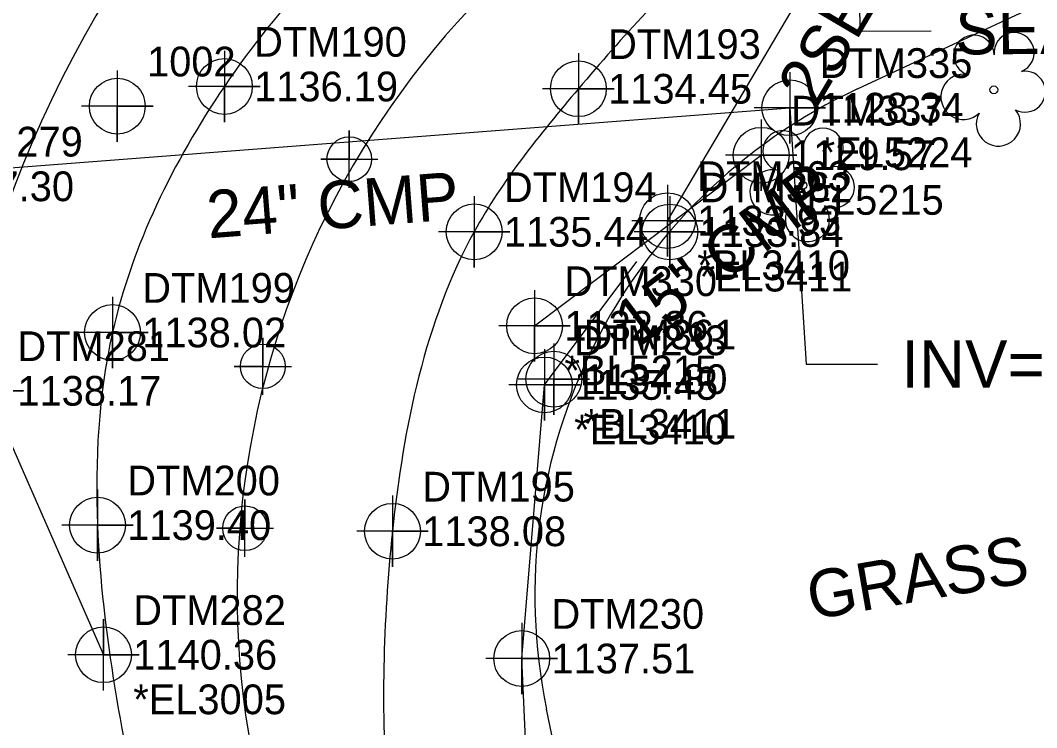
# Model space of a CAD drawing. Extents: x 1286007 to 1287145, y 857718 to 858514.
# Drawn here: x 1286494.9 to 1286580.3, y 858055.9 to 858115.3 of the extents above; entities that cross this region are included whole.
import ezdxf

# ---------------------------------------------------------------- set-up
doc = ezdxf.new("R2010")
doc.units = 0
for name, color, linetype in [('Default Symbol CELL', 7, 'Continuous'), ('Default Symbol Cogo Number', 7, 'Continuous'), ('Exist Horizontal Alignment', 7, 'Continuous'), ('Exist Other Culture Fence Line', 7, 'Continuous'), ('Exist Other Culture Fence Line Cogo Comment', 7, 'Continuous'), ('Exist Other Culture Fence Line Cogo Elevation', 7, 'Continuous'), ('Exist Other Culture Fence Line Cogo Number', 7, 'Continuous'), ('Exist Other Culture Fence Line Cogo Point CELL', 7, 'Continuous'), ('Exist Other Culture Fence Line Text', 7, 'Continuous'), ('Exist Other Culture Gate Cogo Comment', 7, 'Continuous'), ('Exist Other Culture Gate Cogo Elevation', 7, 'Continuous'), ('Exist Other Culture Gate Cogo Number', 7, 'Continuous'), ('Exist Other Culture Gate Cogo Point CELL', 7, 'Continuous'), ('Exist Right of Way Line', 7, 'Continuous'), ('Exist Roads EOP', 7, 'Continuous'), ('Exist Roads EOP Cogo Elevation', 7, 'Continuous'), ('Exist Roads EOP Cogo Number', 7, 'Continuous'), ('Exist Roads EOP Cogo Point CELL', 7, 'Continuous'), ('Exist Roads Soil', 7, 'Continuous'), ('Exist Roads Soil Cogo Comment', 7, 'Continuous'), ('Exist Roads Soil Cogo Elevation', 7, 'Continuous'), ('Exist Roads Soil Cogo Number', 7, 'Continuous'), ('Exist Roads Soil Cogo Point CELL', 7, 'Continuous'), ('Exist Structure Major Bridge Seat Top Elevation', 7, 'Continuous'), ('Exist Structure Minor Pipes CMP 15 Inch', 7, 'Continuous'), ('Exist Structure Minor Pipes CMP 15 Inch Cogo Comment', 7, 'Continuous'), ('Exist Structure Minor Pipes CMP 15 Inch Cogo Elevation', 7, 'Continuous'), ('Exist Structure Minor Pipes CMP 15 Inch Cogo Number', 7, 'Continuous'), ('Exist Structure Minor Pipes CMP 15 Inch Cogo Point CELL', 7, 'Continuous'), ('Exist Structure Minor Pipes CMP 15 Inch Text', 7, 'Continuous'), ('Exist Structure Minor Pipes CMP 24 Inch', 7, 'Continuous'), ('Exist Structure Minor Pipes CMP 24 Inch Cogo Comment', 7, 'Continuous'), ('Exist Structure Minor Pipes CMP 24 Inch Cogo Elevation', 7, 'Continuous'), ('Exist Structure Minor Pipes CMP 24 Inch Cogo Number', 7, 'Continuous'), ('Exist Structure Minor Pipes CMP 24 Inch Cogo Point CELL', 7, 'Continuous'), ('Exist Structure Minor Pipes CMP 24 Inch Invert', 7, 'Continuous'), ('Exist Structure Minor Pipes CMP 24 Inch Text', 7, 'Continuous'), ('Exist Vegetation Tree CELL', 7, 'Continuous'), ('Exist Vegetation Tree Text', 7, 'Continuous'), ('Old_Level_20', 7, 'Continuous')]:
    doc.layers.add(name, color=color, linetype=linetype)

msp = doc.modelspace()

# ---------------------------------------------------------------- linework, layer by layer
at = {"layer": 'Default Symbol CELL'}
for points in [[(1286503.055, 858111.112), (1286503.055, 858105.112), (1286503.055, 858108.112), (1286506.055, 858108.112), (1286500.055, 858108.112)], [(1286503.055, 858111.112), (1286503.055, 858105.112), (1286503.055, 858108.112), (1286506.055, 858108.112), (1286500.055, 858108.112)], [(1286522.535, 858101.26), (1286522.535, 858106.06), (1286522.535, 858103.66), (1286520.135, 858103.66), (1286524.935, 858103.66)], [(1286515.277, 858083.844), (1286515.277, 858088.644), (1286515.277, 858086.244), (1286512.877, 858086.244), (1286517.677, 858086.244)], [(1286513.778, 858070.239), (1286513.778, 858075.039), (1286513.778, 858072.639), (1286511.378, 858072.639), (1286516.178, 858072.639)]]:
    msp.add_lwpolyline(points, dxfattribs=at)
for centre, radius in [((1286503.055, 858108.112), 2.344), ((1286503.055, 858108.112), 2.344), ((1286522.535, 858103.66), 1.875), ((1286515.277, 858086.244), 1.875), ((1286513.778, 858072.639), 1.875)]:
    msp.add_circle(centre, radius, dxfattribs=at)
at = {"layer": 'Exist Horizontal Alignment'}
msp.add_arc((1286585.125, 858066.987), 72, 115.04397, 191.72533, dxfattribs=at)
at = {"layer": 'Exist Other Culture Fence Line'}
msp.add_line((1286549.257, 858098.489), (1286564.961, 858125.103), dxfattribs=at)
for points in [[(1286538.924, 858084.683), (1286546.692, 858095.062)], [(1286547.407, 857964.989), (1286539.472, 858022.106), (1286538.051, 858038.903), (1286537.017, 858061.685), (1286538.924, 858084.683)]]:
    msp.add_lwpolyline(points, dxfattribs=at)
at = {"layer": 'Exist Other Culture Fence Line Cogo Point CELL'}
for points in [[(1286549.257, 858101.489), (1286549.257, 858095.489), (1286549.257, 858098.489), (1286552.257, 858098.489), (1286546.257, 858098.489)], [(1286538.924, 858087.683), (1286538.924, 858081.683), (1286538.924, 858084.683), (1286541.924, 858084.683), (1286535.924, 858084.683)], [(1286537.017, 858064.685), (1286537.017, 858058.685), (1286537.017, 858061.685), (1286540.017, 858061.685), (1286534.017, 858061.685)]]:
    msp.add_lwpolyline(points, dxfattribs=at)
for centre in [(1286549.257, 858098.489), (1286538.924, 858084.683), (1286537.017, 858061.685)]:
    msp.add_circle(centre, 2.344, dxfattribs=at)
at = {"layer": 'Exist Other Culture Gate Cogo Point CELL'}
for points in [[(1286549.458, 858100.537), (1286549.458, 858094.537), (1286549.458, 858097.537), (1286552.458, 858097.537), (1286546.458, 858097.537)], [(1286539.713, 858088.163), (1286539.713, 858082.163), (1286539.713, 858085.163), (1286542.713, 858085.163), (1286536.713, 858085.163)]]:
    msp.add_lwpolyline(points, dxfattribs=at)
for centre in [(1286549.458, 858097.537), (1286539.713, 858085.163)]:
    msp.add_circle(centre, 2.344, dxfattribs=at)
at = {"layer": 'Exist Right of Way Line'}
for p, q in [((1286565.23, 858109.569), (1286654.285, 858151.179)), ((1286558.704, 857963.01), (1286539.106, 858057.436))]:
    msp.add_line(p, q, dxfattribs=at)
for radius in [97, 47]:
    msp.add_arc((1286585.125, 858066.987), radius, 115.04397, 191.72533, dxfattribs=at)
at = {"layer": 'Exist Roads EOP'}
for points in [[(1286554.506, 858138.221), (1286544.419, 858134.401), (1286528.832, 858126.933), (1286512.047, 858109.768), (1286502.652, 858089.088), (1286501.393, 858072.897), (1286505.471, 858045.649), (1286512.056, 858016.522), (1286519.805, 857984.681), (1286525.58, 857958.7)], [(1286561.061, 858127.479), (1286553.633, 858121.854), (1286541.776, 858109.576), (1286533.023, 858097.553), (1286526.163, 858072.381), (1286525.732, 858049.679), (1286530.491, 858019.74), (1286536.523, 857989.722), (1286542.222, 857961.323)]]:
    msp.add_spline(points, degree=3, dxfattribs=at)
at = {"layer": 'Exist Roads EOP Cogo Point CELL'}
for points in [[(1286512.047, 858112.768), (1286512.047, 858106.768), (1286512.047, 858109.768), (1286515.047, 858109.768), (1286509.047, 858109.768)], [(1286541.776, 858112.576), (1286541.776, 858106.576), (1286541.776, 858109.576), (1286544.776, 858109.576), (1286538.776, 858109.576)], [(1286533.023, 858100.553), (1286533.023, 858094.553), (1286533.023, 858097.553), (1286536.023, 858097.553), (1286530.023, 858097.553)], [(1286502.652, 858092.088), (1286502.652, 858086.088), (1286502.652, 858089.088), (1286505.652, 858089.088), (1286499.652, 858089.088)], [(1286501.393, 858075.897), (1286501.393, 858069.897), (1286501.393, 858072.897), (1286504.393, 858072.897), (1286498.393, 858072.897)], [(1286526.163, 858075.381), (1286526.163, 858069.381), (1286526.163, 858072.381), (1286529.163, 858072.381), (1286523.163, 858072.381)]]:
    msp.add_lwpolyline(points, dxfattribs=at)
for centre in [(1286512.047, 858109.768), (1286541.776, 858109.576), (1286533.023, 858097.553), (1286502.652, 858089.088), (1286501.393, 858072.897), (1286526.163, 858072.381)]:
    msp.add_circle(centre, 2.344, dxfattribs=at)
at = {"layer": 'Exist Roads Soil'}
msp.add_lwpolyline([(1286451.264, 858136.048), (1286463.084, 858125.359), (1286484.836, 858101.378), (1286492.165, 858084.188), (1286501.894, 858062.005)], dxfattribs=at)
at = {"layer": 'Exist Roads Soil Cogo Point CELL'}
for points in [[(1286492.165, 858081.188), (1286492.165, 858087.188), (1286492.165, 858084.188), (1286495.165, 858084.188), (1286489.165, 858084.188)], [(1286501.894, 858059.005), (1286501.894, 858065.005), (1286501.894, 858062.005), (1286504.894, 858062.005), (1286498.894, 858062.005)]]:
    msp.add_lwpolyline(points, dxfattribs=at)
msp.add_circle((1286501.894, 858062.005), 2.344, dxfattribs=at)
at = {"layer": 'Exist Structure Major Bridge Seat Top Elevation'}
msp.add_lwpolyline([(1286565.278, 858126.616), (1286565.417, 858114.423), (1286571.417, 858114.452)], dxfattribs=at)
at = {"layer": 'Exist Structure Minor Pipes CMP 15 Inch'}
msp.add_line((1286538.1, 858089.65), (1286557.128, 858103.986), dxfattribs=at)
at = {"layer": 'Exist Structure Minor Pipes CMP 15 Inch Cogo Point CELL'}
for points in [[(1286557.128, 858106.986), (1286557.128, 858100.986), (1286557.128, 858103.986), (1286560.128, 858103.986), (1286554.128, 858103.986)], [(1286538.1, 858092.65), (1286538.1, 858086.65), (1286538.1, 858089.65), (1286541.1, 858089.65), (1286535.1, 858089.65)]]:
    msp.add_lwpolyline(points, dxfattribs=at)
for centre in [(1286557.128, 858103.986), (1286538.1, 858089.65)]:
    msp.add_circle(centre, 2.344, dxfattribs=at)
at = {"layer": 'Exist Structure Minor Pipes CMP 24 Inch'}
msp.add_line((1286469.96, 858101.075), (1286559.538, 858107.984), dxfattribs=at)
at = {"layer": 'Exist Structure Minor Pipes CMP 24 Inch Cogo Point CELL'}
msp.add_lwpolyline([(1286559.538, 858110.984), (1286559.538, 858104.984), (1286559.538, 858107.984), (1286562.538, 858107.984), (1286556.538, 858107.984)], dxfattribs=at)
msp.add_circle((1286559.538, 858107.984), 2.344, dxfattribs=at)
at = {"layer": 'Exist Structure Minor Pipes CMP 24 Inch Invert'}
msp.add_lwpolyline([(1286559.538, 858107.984), (1286560.897, 858086.441), (1286566.897, 858086.441)], dxfattribs=at)
at = {"layer": 'Exist Vegetation Tree CELL'}
for p, q in [((1286576.666, 858109.487), (1286576.666, 858109.487)), ((1286560.627, 858101.459), (1286560.627, 858101.459))]:
    msp.add_line(p, q, dxfattribs=at)
for centre in [(1286576.666, 858109.487), (1286560.627, 858101.459)]:
    msp.add_circle(centre, 0.326, dxfattribs=at)
for centre, radius, start, end in [((1286574.993, 858112.386), 1.698, 1.28216, 254.55999), ((1286578.37, 858112.608), 1.689, 291.56708, 186.23104), ((1286574.117, 858108.898), 1.899, 77.1011, 314.19993), ((1286579.271, 858109.333), 1.727, 242.66361, 99.3457), ((1286577.05, 858106.613), 1.856, 150.16508, 39.71335), ((1286558.954, 858104.358), 1.698, 1.28216, 254.55999), ((1286562.331, 858104.579), 1.689, 291.56708, 186.23104), ((1286563.232, 858101.305), 1.727, 242.66361, 99.3457), ((1286558.078, 858100.87), 1.899, 77.1011, 314.19993), ((1286561.012, 858098.585), 1.856, 150.16508, 39.71335)]:
    msp.add_arc(centre, radius, start, end, dxfattribs=at)
at = {"layer": 'Old_Level_20'}
msp.add_arc((1286585.125, 858066.987), 72, 115.04397, 191.72533, dxfattribs=at)

# ---------------------------------------------------------------- texts
at = {"layer": 'Default Symbol Cogo Number'}
msp.add_text('1002', height=2.5, dxfattribs=at).set_placement((1286505.555, 858110.612))
at = {"layer": 'Exist Other Culture Fence Line Cogo Comment'}
for s, p in [('*BL3410', (1286551.757, 858093.489)), ('*EL3410', (1286541.424, 858079.683))]:
    msp.add_text(s, height=2.5, dxfattribs=at).set_placement(p)
at = {"layer": 'Exist Other Culture Fence Line Cogo Elevation'}
for s, p in [('1133.93', (1286551.757, 858097.239)), ('1135.45', (1286541.424, 858083.433)), ('1137.51', (1286539.517, 858060.435))]:
    msp.add_text(s, height=2.5, dxfattribs=at).set_placement(p)
at = {"layer": 'Exist Other Culture Fence Line Cogo Number'}
for s, p in [('DTM363', (1286551.757, 858100.989)), ('DTM233', (1286541.424, 858087.183)), ('DTM230', (1286539.517, 858064.185))]:
    msp.add_text(s, height=2.5, dxfattribs=at).set_placement(p)
at = {"layer": 'Exist Other Culture Fence Line Text'}
msp.add_text('2SE', height=4, rotation=59.45662, dxfattribs=at).set_placement((1286561.774, 858107.895))
at = {"layer": 'Exist Other Culture Gate Cogo Comment'}
for s, p in [('*EL3411', (1286551.958, 858092.537)), ('*BL3411', (1286542.213, 858080.163))]:
    msp.add_text(s, height=2.5, dxfattribs=at).set_placement(p)
at = {"layer": 'Exist Other Culture Gate Cogo Elevation'}
for s, p in [('1133.84', (1286551.958, 858096.287)), ('1134.80', (1286542.213, 858083.913))]:
    msp.add_text(s, height=2.5, dxfattribs=at).set_placement(p)
at = {"layer": 'Exist Other Culture Gate Cogo Number'}
for s, p in [('DTM362', (1286551.958, 858100.037)), ('DTM361', (1286542.213, 858087.663))]:
    msp.add_text(s, height=2.5, dxfattribs=at).set_placement(p)
at = {"layer": 'Exist Roads EOP Cogo Elevation'}
for s, p in [('1136.19', (1286514.547, 858108.518)), ('1134.45', (1286544.276, 858108.326)), ('1135.44', (1286535.523, 858096.303)), ('1138.02', (1286505.152, 858087.838)), ('1139.40', (1286503.893, 858071.647)), ('1138.08', (1286528.663, 858071.131))]:
    msp.add_text(s, height=2.5, dxfattribs=at).set_placement(p)
at = {"layer": 'Exist Roads EOP Cogo Number'}
for s, p in [('DTM190', (1286514.547, 858112.268)), ('DTM193', (1286544.276, 858112.076)), ('DTM194', (1286535.523, 858100.053)), ('DTM199', (1286505.152, 858091.588)), ('DTM200', (1286503.893, 858075.397)), ('DTM195', (1286528.663, 858074.881))]:
    msp.add_text(s, height=2.5, dxfattribs=at).set_placement(p)
at = {"layer": 'Exist Roads Soil Cogo Comment'}
msp.add_text('*EL3005', height=2.5, dxfattribs=at).set_placement((1286504.394, 858057.005))
at = {"layer": 'Exist Roads Soil Cogo Elevation'}
for s, p in [('1137.30', (1286487.336, 858100.128)), ('1138.17', (1286494.665, 858082.938)), ('1140.36', (1286504.394, 858060.755))]:
    msp.add_text(s, height=2.5, dxfattribs=at).set_placement(p)
at = {"layer": 'Exist Roads Soil Cogo Number'}
for s, p in [('DTM279', (1286487.336, 858103.878)), ('DTM281', (1286494.665, 858086.688)), ('DTM282', (1286504.394, 858064.505))]:
    msp.add_text(s, height=2.5, dxfattribs=at).set_placement(p)
at = {"layer": 'Exist Structure Major Bridge Seat Top Elevation'}
msp.add_text("SEAT=1130.21'", height=4, rotation=0.27184, dxfattribs=at).set_placement((1286573.426, 858112.461))
at = {"layer": 'Exist Structure Minor Pipes CMP 15 Inch Cogo Comment'}
for s, p in [('*EL5215', (1286559.628, 858098.986)), ('*BL5215', (1286540.6, 858084.65))]:
    msp.add_text(s, height=2.5, dxfattribs=at).set_placement(p)
at = {"layer": 'Exist Structure Minor Pipes CMP 15 Inch Cogo Elevation'}
for s, p in [('1129.57', (1286559.628, 858102.736)), ('1132.86', (1286540.6, 858088.4))]:
    msp.add_text(s, height=2.5, dxfattribs=at).set_placement(p)
at = {"layer": 'Exist Structure Minor Pipes CMP 15 Inch Cogo Number'}
for s, p in [('DTM337', (1286559.628, 858106.486)), ('DTM330', (1286540.6, 858092.15))]:
    msp.add_text(s, height=2.5, dxfattribs=at).set_placement(p)
at = {"layer": 'Exist Structure Minor Pipes CMP 15 Inch Text'}
msp.add_text('15" CMP', height=4, rotation=36.99496, dxfattribs=at).set_placement((1286546.75, 858087.715))
at = {"layer": 'Exist Structure Minor Pipes CMP 24 Inch Cogo Comment'}
msp.add_text('*EL5224', height=2.5, dxfattribs=at).set_placement((1286562.038, 858102.984))
at = {"layer": 'Exist Structure Minor Pipes CMP 24 Inch Cogo Elevation'}
msp.add_text('1128.34', height=2.5, dxfattribs=at).set_placement((1286562.038, 858106.734))
at = {"layer": 'Exist Structure Minor Pipes CMP 24 Inch Cogo Number'}
msp.add_text('DTM335', height=2.5, dxfattribs=at).set_placement((1286562.038, 858110.484))
at = {"layer": 'Exist Structure Minor Pipes CMP 24 Inch Invert'}
msp.add_text("INV=1128.34'", height=4, dxfattribs=at).set_placement((1286568.897, 858084.441))
at = {"layer": 'Exist Structure Minor Pipes CMP 24 Inch Text'}
msp.add_text('24" CMP', height=4, rotation=4.4104, dxfattribs=at).set_placement((1286510.715, 858096.997))
at = {"layer": 'Exist Vegetation Tree Text'}
msp.add_text('GRASS', height=4, rotation=9.84403, dxfattribs=at).set_placement((1286561.364, 858064.927))

doc.saveas('drawing.dxf')
